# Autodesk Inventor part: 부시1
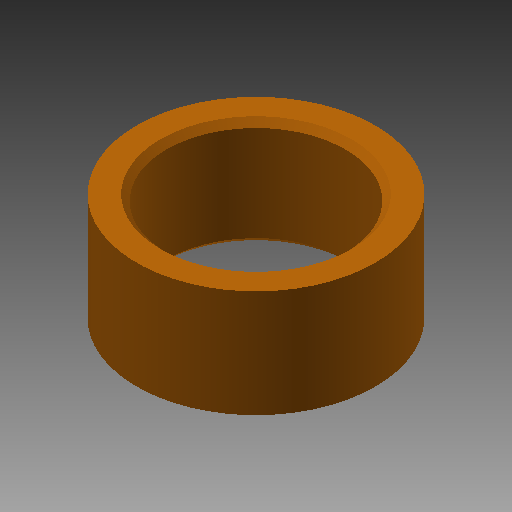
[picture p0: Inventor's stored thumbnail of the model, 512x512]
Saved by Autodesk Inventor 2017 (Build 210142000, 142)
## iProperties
Created: 2016-08
Part Number: 부시1
Material: 강철, 탄소
Document SubType Name: Modeling
Designer: mduedu
Density: 7.87 g/cm^3
Appearance: 주황색
Author: mduedu
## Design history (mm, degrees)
sketch "스케치1"
  geometry: C1 r 7.5 at (0, 0); C2 r 10 at (0, 0); 1 further point
  constraints: 2 centre point, 2 coincident
  dimensions: "d0" = 15 diameter of C1; "d1" = 20 diameter of C2
extrude "돌출1" new body sketch "스케치1" stored distance "d2" = 9; taper "d3" = 0 deg
chamfer "모따기1" distance "d4" = 0.5; stored, may be unused: second distance "d5" = 2, angle "d6" = 45 deg
node "솔리드1"
